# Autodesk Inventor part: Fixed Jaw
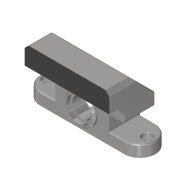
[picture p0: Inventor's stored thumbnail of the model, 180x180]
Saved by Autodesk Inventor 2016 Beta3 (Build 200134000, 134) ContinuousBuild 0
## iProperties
Created: 2016-02
Part Number: Fixed Jaw
Material: Steel, Cast
Document SubType Name: Modeling
Designer: Vertex
Mass: 2584.79 g
Surface Area: 444.62 cm^2
Volume: 329.273 cm^3
Density: 7.85 g/cm^3
Appearance: Semi-Polished
Title: Apoio
Author: Vertex
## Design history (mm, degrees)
sketch "Sketch1"
  geometry: L1 (75, 80)-(25, 80); L2 (0, 15)-(0, 0); L3 (0, 15)-(40, 15); L4 (40, 35)-(40, 15); L5 (20, 35)-(40, 35); L6 (20, 75)-(20, 35); L7 (20, 75)-(25, 80); L8 (75, 80)-(125, 80); L9 (150, 15)-(150, 0); L10 (150, 15)-(110, 15); L11 (110, 35)-(110, 15); L12 (130, 35)-(110, 35); L13 (130, 75)-(130, 35); L14 (130, 75)-(125, 80); L15 (0, 0)-(150, 0); L16 (75, 50.194)-(75, -5); 5 further points
  constraints: 32 end point, 6 point on line, 2 parallel, 1 horizontal, 1 vertical
  dimensions: "d3" = 40 distance between parallel lines of L2 L4; "d5" = 5 distance of L6.start point (20, 80); "d6" = 5 distance of L1.end point (20, 80) (= d5); "d7" = 150 distance of L9.end L2.end; "d8" = 130 distance of point (140, 15) point (10, 15); "d9" = 20 distance between parallel lines of L12 L10; "d10" = 45 distance from line of L8 L12.start; "d67" = 15 distance of L9.end L9.start; "d68" = 45 vertical distance of L5.start L1.end
extrude "Extrusion1" new body sketch "Sketch1" stored distance "d11" = 40; taper "d12" = 0 deg
hole "Hole1" diameter "d15" = 26; stored, may be unused: countersink angle "d19" = 90 deg, drill point angle "d21" = 118 deg; dims "d13" = 75, "d14" = 25, "d16" = 7.5, "d17" = 3.75, "d18" = 2.5, "d20" = 30
hole "Hole2" diameter "d24" = 8; stored, may be unused: countersink angle "d28" = 90 deg, drill point angle "d30" = 118 deg; dims "d22" = 10, "d23" = 20, "d25" = 7.5, "d26" = 13.5, "d27" = 5, "d29" = 10
workplane "Work Plane1"
mirror "Mirror1"
sketch "Sketch2"
  geometry: C1 r 20 at (75, 25); C2 r 16 at (75, 25); 2 further points
  constraints: 2 centre point, 2 coincident
  dimensions: "d34" = 40 diameter of C1; "d40" = 32 diameter of C2
extrude "Extrusion2" join sketch "Sketch2" distance "d35" = 5; taper "d36" = 0 deg
chamfer "Chamfer3" distance "d41" = 2.5; stored, may be unused: second distance "d42" = 1.25, angle "d43" = 45 deg
fillet "Fillet6" dims "d66" = 0.5
chamfer "Chamfer4" distance "d69" = 30; stored, may be unused: second distance "d70" = 1.25, angle "d71" = 45 deg
fillet "Fillet8"
fillet "Fillet9"
fillet "Fillet10" dims "d72" = 2
sketch "Sketch3"
  geometry: L1 (22, 35)-(40, 35) reference; L2 (40, 35)-(40, 13) reference; L3 (20, 13)-(40, 13) reference; L4 (20, 0)-(20, 13) reference; L5 (20, 0)-(130, 0) reference; L6 (130, 13)-(130, 0) reference; L7 (110, 13)-(130, 13) reference; L8 (110, 35)-(110, 13) reference; L9 (110, 35)-(128, 35) reference; L10 (130, 37)-(130, 74.172) reference; L11 (129.414, 75.586)-(125.586, 79.414) reference; L12 (124.172, 80)-(25.828, 80) reference; L13 (24.414, 79.414)-(20.586, 75.586) reference; L14 (20, 74.172)-(20, 37) reference; L15 (20, 74.172)-(20, 37) reference; L16 (20, 55)-(130, 55); L17 (130, 37)-(130, 74.172) reference; C1 r 20 at (75, 25) reference; A1 r 2 centre (22, 37) between (20, 37) and (22, 35) reference; A2 r 2 centre (128, 37) between (128, 35) and (130, 37) reference; A3 r 2 centre (128, 74.172) between (130, 74.172) and (129.414, 75.586) reference; A4 r 2 centre (124.172, 78) between (125.586, 79.414) and (124.172, 80) reference; A5 r 2 centre (25.828, 78) between (25.828, 80) and (24.414, 79.414) reference; A6 r 2 centre (22, 74.172) between (20.586, 75.586) and (20, 74.172) reference; 1 further point
  constraints: 2 end point, 2 point on line, 1 perpendicular
extrude "Extrusion3" join sketch "Sketch3" distance "d73" = 20; taper "d74" = 0 deg
chamfer "Chamfer5" distance "d75" = 10; stored, may be unused: second distance "d76" = 1.25, angle "d77" = 45 deg
hole "Hole5" diameter "d80" = 4.92; stored, may be unused: countersink angle "d84" = 90 deg, drill point angle "d86" = 118 deg; dims "d78" = 10, "d79" = 10, "d81" = 12, "d82" = 3.75, "d83" = 2.5, "d85" = 20
mirror "Mirror6"
mirror "Mirror7"
body "Solid1"
node "Projected Loop1"
